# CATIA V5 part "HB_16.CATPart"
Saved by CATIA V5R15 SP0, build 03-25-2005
Part number: HB_16
Material "Blue": density 7860 kg/m3, Young's modulus 2e+11 Pa, Poisson ratio 0.266
Bounding box of the stored display mesh (mm): x -79 to 0, y 0 to 1264, z 0 to 113.2
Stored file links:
  E:\#01 CATIA Lecture Materials\#06 DMU\#11 DMU Page01 KIN EX11\HB_16.CATPart
  E:\공학과제\HB-16.CATPart
  C:\Program Files\Dassault Systemes\B20\win_b64\startup\materials\Catalog.CATMaterial
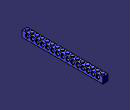
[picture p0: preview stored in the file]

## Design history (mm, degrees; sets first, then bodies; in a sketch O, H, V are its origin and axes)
Body1 (main body), material "Blue"
  Sketch1 on xy-plane, origin (0, 0, 0), H (1, 0, 0), V (0, 1, 0)
    circle A1 centre (-39.5, 39.5) radius 24.5
    point P1 (-39.5, 39.5)
    reference projected line E1 (0, 0) -> (0, 1264)
    reference projected line E2 (-79, 0) -> (-79, 1264)
    reference projected line E3 (-79, 0) -> (0, 0)
    radius A1 = 24.5
    distance P1 E3 = 39.5
    equidistance: E1 E2 P1
  Pad1: profile Sketch1, direction (0, 0, 1), length 113.2
  RectPattern1: of the body so far, direction 1 instances 16, spacing 79, along yz-plane
  Sketch2 on zx-plane, origin (0, 0, 0), H (-1, 0, 0), V (0, 0, 1)
    point P1 (0, 96)
    line L1 (0, 96) -> (79, 96)
    line L2 (79, 96) -> (79, 0)
    line L3 (79, 0) -> (0, 0)
    line L4 (0, 0) -> (0, 96)
    point P3 (79, 0)
    distance L2 L4 = 79
    length L2 = 96
    coincidence: P1 V, P3 H
    horizontal: L1 H, L3 H
    vertical: L2 V, L4 V
  Pad2: profile Sketch2, direction (0, 1, 0), length 1264 {= RectPattern1.Nb1 * (79*1mm)}
  Plane1: type Offset, RefPlane zx-plane, Offset 79
  Sketch3 on Plane1, origin (0, 79, 0), H (-1, 0, 0), V (0, 0, 1)
    axis line L1 (95.3003, 56) -> (-23.8651, 56)
    reference projected line E1 (79, 96) -> (0, 96) from edge [start face of Pad2 | face of Pad2 from Sketch2.L1]
    point P3 (79, 56)
    line L2 (79, 56) -> (79, 85.25)
    line L3 (79, 85.25) -> (69, 85.25)
    line L4 (69, 85.25) -> (69, 80.25)
    line L5 (69, 80.25) -> (10, 80.25)
    line L6 (10, 80.25) -> (10, 85.25)
    point P8 (10, 85.25)
    line L7 (10, 85.25) -> (0, 85.25)
    point P9 (0, 85.25)
    line L8 (0, 85.25) -> (0, 56)
    point P10 (0, 56)
    reference projected line E2 (79, 0) -> (79, 96) from edge [start face of Pad2 | face of Pad2 from Sketch2.L2]
    distance L1 E1 = 40
    distance L8 L6 = 10
    distance L4 L2 = 10
    distance L5 L1 = 24.25
    distance L7 L1 = 29.25
    horizontal: L1 H, L3 H, L5 H, L7 H
    coincidence: P3 L1, P8 L3, P9 V, P10 L1, L2 E2
    vertical: L2 V, L4 V, L6 V, L8 V
  Groove1: profile Sketch3, axis Sketch3.L1, angle 360
  RectPattern2: of Groove1, direction 1 instances 15 {= RectPattern1.Nb1 - 1}, spacing 79, along edge [face of Pad2 from Sketch2.L4 | face of Pad2 from Sketch2.L1]
  Shell1: ExtOffset 0, Face face of Pad2, IntOffset 10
